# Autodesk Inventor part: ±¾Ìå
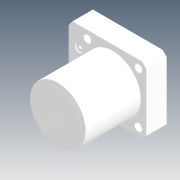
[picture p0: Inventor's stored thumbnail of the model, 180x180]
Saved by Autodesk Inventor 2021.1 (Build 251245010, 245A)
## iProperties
Created: 2021-05
Part Number: ±¾Ìå
Material: Ogólny
Document SubType Name: Modeling
Designer: user
Density: 1 g/cm^3
Appearance: Domyślna
Author: user
Revision Number: ÈÎºÎ
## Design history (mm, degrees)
feature "NONE"
feature "NONE:1"
feature "Złożony1"
node "Bryła1"
node "Bryła2"
body "Srf1"
